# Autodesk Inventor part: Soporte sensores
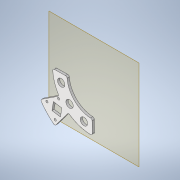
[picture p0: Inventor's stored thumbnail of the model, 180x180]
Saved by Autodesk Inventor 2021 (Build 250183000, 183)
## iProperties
Created: 2021-03
Part Number: Soporte sensores
Material: Genérico
Document SubType Name: Modeling
Designer: ATOUZA
Density: 1 g/cm^3
Appearance: Valor por defecto
Author: ATOUZA
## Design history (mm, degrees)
node "Plano de trabajo1"
sketch "Boceto1"
  geometry: L1 (-28.693, -55.468)-(-54.544, -30.413) reference; L2 (-79.599, -56.264)-(-53.748, -81.319) reference; L3 (0, 0)-(-54.146, -55.866); L4 (0, 0)-(-18.974, -75.514); L5 (0, 0)-(-74.556, -21.232); L6 (0, 0)-(-95.288, -1.49); L7 (0, 0)-(1.49, -95.288); L8 (-88.281, -84.164)-(-87.637, -83.606) reference; L9 (-87.223, -81.124)-(-87.653, -80.388) reference; L10 (-86.41, -79.502)-(-85.857, -80.148) reference; L11 (-83.375, -80.561)-(-82.642, -80.129) reference; L12 (-81.755, -81.37)-(-82.399, -81.927) reference; L13 (-82.813, -84.41)-(-82.383, -85.146) reference; L14 (-83.625, -86.032)-(-84.179, -85.386) reference; L15 (-86.661, -84.972)-(-87.393, -85.405) reference; L16 (-83.338, -78.485)-(-81.09, -78.859) reference; L17 (-84.256, -78.8)-(-83.441, -78.495) reference; L18 (-85.125, -78.214)-(-84.453, -78.767) reference; L19 (-87.467, -77.797)-(-85.219, -78.171) reference; L20 (-89.656, -74.985)-(-87.792, -77.595) reference; L21 (-89.622, -73.89)-(-89.743, -74.612) reference; L22 (-87.173, -73.791)-(-89.047, -73.479) reference; L23 (-86.548, -73.084)-(-86.597, -73.38) reference; L24 (-87.058, -72.796)-(-86.713, -72.854) reference; L25 (-87.008, -72.5)-(-87.058, -72.796) reference; L26 (-91.76, -71.506)-(-87.173, -72.27) reference; L27 (-94.25, -77.326)-(-93.486, -72.74) reference; L28 (-93.789, -77.606)-(-94.085, -77.557) reference; L29 (-93.847, -77.951)-(-93.789, -77.606) reference; L30 (-93.386, -78.231)-(-93.682, -78.181) reference; L31 (-92.499, -75.945)-(-92.811, -77.819) reference; L32 (-91.201, -75.655)-(-91.924, -75.534) reference; L33 (-89.012, -78.467)-(-90.877, -75.857) reference; L34 (-89.3, -81.087)-(-88.926, -78.839) reference; L35 (-88.985, -82.005)-(-89.29, -81.19) reference; L36 (-89.571, -82.874)-(-89.018, -82.202) reference; L37 (-89.988, -85.216)-(-89.613, -82.968) reference; L38 (-92.8, -87.405)-(-90.19, -85.541) reference; L39 (-93.895, -87.371)-(-93.173, -87.491) reference; L40 (-93.994, -84.922)-(-94.306, -86.796) reference; L41 (-94.701, -84.297)-(-94.405, -84.346) reference; L42 (-94.988, -84.807)-(-94.931, -84.461) reference; L43 (-95.284, -84.757)-(-94.988, -84.807) reference; L44 (-96.278, -89.509)-(-95.515, -84.922) reference; L45 (-90.458, -91.999)-(-95.045, -91.235) reference; L46 (-90.179, -91.538)-(-90.228, -91.834) reference; L47 (-89.834, -91.596)-(-90.179, -91.538) reference; L48 (-89.554, -91.135)-(-89.604, -91.431) reference; L49 (-91.84, -90.248)-(-89.965, -90.56) reference; L50 (-92.13, -88.95)-(-92.251, -89.673) reference; L51 (-89.318, -86.761)-(-91.928, -88.626) reference; L52 (-86.698, -87.049)-(-88.945, -86.675) reference; L53 (-85.78, -86.734)-(-86.595, -87.039) reference; L54 (-84.911, -87.32)-(-85.583, -86.767) reference; L55 (-82.569, -87.737)-(-84.817, -87.362) reference; L56 (-80.38, -90.549)-(-82.244, -87.939) reference; L57 (-80.414, -91.644)-(-80.293, -90.922) reference; L58 (-82.863, -91.743)-(-80.989, -92.055) reference; L59 (-83.488, -92.45)-(-83.438, -92.154) reference; L60 (-82.978, -92.737)-(-83.323, -92.68) reference; L61 (-83.027, -93.033)-(-82.978, -92.737) reference; L62 (-78.276, -94.027)-(-82.863, -93.263) reference; L63 (-75.786, -88.207)-(-76.55, -92.794) reference; L64 (-76.247, -87.928)-(-75.951, -87.977) reference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; C1 r 2 at (-54.146, -55.866) reference; C2 r 9 at (-54.146, -55.866); C3 r 9 at (-18.974, -75.514); C4 r 9 at (-74.556, -21.232); C5 r 9 at (-54.146, -55.866); C6 r 9 at (-18.974, -75.514); C7 r 2.75 at (-109.382, -78.709); C8 r 2.75 at (-80.96, -58.402); C9 r 2.75 at (-89.075, -107.131); C10 r 2.75 at (-89.075, -107.131); C11 r 2.75 at (-109.382, -78.709); C12 r 2.75 at (-80.96, -58.402); A1 r 60.3 centre (0, 0) between (-60.293, -0.943) and (0.943, -60.293); A2 r 95.3 centre (0, 0) between (-69.394, -65.319) and (-79.682, -52.277); A3 r 60.3 centre (0, 0) between (-60.293, -0.943) and (0.943, -60.293); A4 r 2.75 centre (-85.018, -82.767) between (-87.223, -81.124) and (-87.637, -83.606) reference; A5 r 3.55 centre (-85.018, -82.767) between (-86.41, -79.502) and (-87.653, -80.388) reference; A6 r 2.75 centre (-85.018, -82.767) between (-83.375, -80.561) and (-85.857, -80.148) reference; A7 r 3.55 centre (-85.018, -82.767) between (-81.755, -81.37) and (-82.642, -80.129) reference; A8 r 2.75 centre (-85.018, -82.767) between (-82.813, -84.41) and (-82.399, -81.927) reference; A9 r 3.55 centre (-85.018, -82.767) between (-83.625, -86.032) and (-82.383, -85.146) reference; A10 r 2.75 centre (-85.018, -82.767) between (-86.661, -84.972) and (-84.179, -85.386) reference; A11 r 3.55 centre (-85.018, -82.767) between (-88.281, -84.164) and (-87.393, -85.405) reference; A12 r 0.2 centre (-84.326, -78.613) between (-84.453, -78.767) and (-84.256, -78.8) reference; A13 r 0.2 centre (-85.252, -78.369) between (-85.125, -78.214) and (-85.219, -78.171) reference; A14 r 0.5 centre (-87.385, -77.304) between (-87.792, -77.595) and (-87.467, -77.797) reference; A15 r 0.5 centre (-89.249, -74.694) between (-89.743, -74.612) and (-89.656, -74.985) reference; A16 r 0.5 centre (-89.129, -73.972) between (-89.047, -73.479) and (-89.622, -73.89) reference; A17 r 0.5 centre (-87.091, -73.298) between (-87.173, -73.791) and (-86.597, -73.38) reference; A18 r 0.2 centre (-86.745, -73.051) between (-86.548, -73.084) and (-86.713, -72.854) reference; A19 r 0.2 centre (-87.206, -72.468) between (-87.008, -72.5) and (-87.173, -72.27) reference; A20 r 1.5 centre (-92.006, -72.986) between (-91.76, -71.506) and (-93.486, -72.74) reference; A21 r 0.2 centre (-94.052, -77.359) between (-94.25, -77.326) and (-94.085, -77.557) reference; A22 r 0.2 centre (-93.65, -77.984) between (-93.847, -77.951) and (-93.682, -78.181) reference; A23 r 0.5 centre (-93.304, -77.737) between (-93.386, -78.231) and (-92.811, -77.819) reference; A24 r 0.5 centre (-92.006, -76.027) between (-91.924, -75.534) and (-92.499, -75.945) reference; A25 r 0.5 centre (-91.283, -76.148) between (-90.877, -75.857) and (-91.201, -75.655) reference; A26 r 0.5 centre (-89.419, -78.757) between (-88.926, -78.839) and (-89.012, -78.467) reference; A27 r 0.2 centre (-89.103, -81.12) between (-89.3, -81.087) and (-89.29, -81.19) reference; A28 r 0.2 centre (-89.172, -82.075) between (-89.018, -82.202) and (-88.985, -82.005) reference; A29 r 0.5 centre (-90.481, -85.134) between (-90.19, -85.541) and (-89.988, -85.216) reference; A30 r 0.5 centre (-93.09, -86.998) between (-93.173, -87.491) and (-92.8, -87.405) reference; A31 r 0.5 centre (-93.813, -86.878) between (-94.306, -86.796) and (-93.895, -87.371) reference; A32 r 0.5 centre (-94.487, -84.84) between (-93.994, -84.922) and (-94.405, -84.346) reference; A33 r 0.2 centre (-94.734, -84.494) between (-94.701, -84.297) and (-94.931, -84.461) reference; A34 r 0.2 centre (-95.317, -84.955) between (-95.284, -84.757) and (-95.515, -84.922) reference; A35 r 1.5 centre (-94.799, -89.755) between (-96.278, -89.509) and (-95.045, -91.235) reference; A36 r 0.2 centre (-90.426, -91.801) between (-90.458, -91.999) and (-90.228, -91.834) reference; A37 r 0.2 centre (-89.801, -91.398) between (-89.834, -91.596) and (-89.604, -91.431) reference; A38 r 0.5 centre (-90.047, -91.053) between (-89.554, -91.135) and (-89.965, -90.56) reference; A39 r 0.5 centre (-91.757, -89.755) between (-92.251, -89.673) and (-91.84, -90.248) reference; A40 r 0.5 centre (-91.637, -89.032) between (-91.928, -88.626) and (-92.13, -88.95) reference; A41 r 0.5 centre (-89.028, -87.168) between (-88.945, -86.675) and (-89.318, -86.761) reference; A42 r 0.2 centre (-86.665, -86.852) between (-86.698, -87.049) and (-86.595, -87.039) reference; A43 r 0.2 centre (-85.71, -86.921) between (-85.583, -86.767) and (-85.78, -86.734) reference; A44 r 0.2 centre (-84.784, -87.165) between (-84.911, -87.32) and (-84.817, -87.362) reference; A45 r 0.5 centre (-82.651, -88.23) between (-82.244, -87.939) and (-82.569, -87.737) reference; A46 r 0.5 centre (-80.787, -90.839) between (-80.293, -90.922) and (-80.38, -90.549) reference; A47 r 0.5 centre (-80.907, -91.562) between (-80.989, -92.055) and (-80.414, -91.644) reference; A48 r 0.5 centre (-82.945, -92.236) between (-82.863, -91.743) and (-83.438, -92.154) reference; A49 r 0.2 centre (-83.29, -92.483) between (-83.488, -92.45) and (-83.323, -92.68) reference; A50 r 0.2 centre (-82.83, -93.066) between (-83.027, -93.033) and (-82.863, -93.263) reference; A51 r 1.5 centre (-78.03, -92.548) between (-78.276, -94.027) and (-76.55, -92.794) reference; A52 r 0.2 centre (-75.984, -88.174) between (-75.786, -88.207) and (-75.951, -87.977) reference; A53 r 0.2 centre (-76.386, -87.55) between (-76.189, -87.583) and (-76.354, -87.353) reference; A54 r 0.5 centre (-76.732, -87.796) between (-76.649, -87.303) and (-77.225, -87.714) reference; A55 r 0.5 centre (-78.03, -89.506) between (-78.112, -90) and (-77.537, -89.588) reference; A56 r 0.5 centre (-78.752, -89.386) between (-79.159, -89.677) and (-78.835, -89.879) reference; A57 r 0.5 centre (-80.617, -86.777) between (-81.11, -86.694) and (-81.024, -87.067) reference; A58 r 0.2 centre (-80.933, -84.414) between (-80.736, -84.447) and (-80.746, -84.344) reference; A59 r 0.2 centre (-80.864, -83.459) between (-81.018, -83.332) and (-81.051, -83.529) reference; A60 r 0.2 centre (-80.62, -82.533) between (-80.465, -82.66) and (-80.422, -82.565) reference; A61 r 0.5 centre (-79.555, -80.4) between (-79.846, -79.993) and (-80.048, -80.318) reference; A62 r 0.5 centre (-76.945, -78.535) between (-76.863, -78.042) and (-77.236, -78.129) reference; A63 r 0.5 centre (-76.223, -78.656) between (-75.73, -78.738) and (-76.141, -78.163) reference; A64 r 0.5 centre (-75.549, -80.694) between (-76.042, -80.612) and (-75.631, -81.187) reference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; 2 further points
  constraints: 40 end point, 18 centre point, 17 coincident, 17 point on circle, 6 midpoint, 5 point on line, 4 concentric, 3 parallel, 2 collinear, 2 perpendicular
  dimensions: "d0" = 18 diameter of C2; "d1" = 30 deg angle of L4 L3; "d2" = 18 diameter of C3; "d3" = 30 deg angle of L3 L5; "d4" = 18 diameter of C4; "d6" = 15 deg angle of L6 L5; "d7" = 15 deg angle of L7 L4; "d8" = 21 distance between parallel lines of L90 L88; "d9" = 21 distance between parallel lines of L91 L89; "d10" = 10 deg angle of L94 L95; "d12" = 150 radius of A74; "d14" = 10 deg angle of L96 L94; "d16" = 14.2 distance of L97.start L97.end; "d18" = 14.2 distance of L98.start L98.end; "d19" = 14.2 distance of L99.start L99.end; "d20" = 14.2 distance of L100.start L100.end; "d21" = 5.5 diameter of C7; "d22" = 5.5 diameter of C8; "d23" = 5.5 diameter of C9
extrude "Extrusión1" new body sketch "Boceto1" distance "d24" = 5.5; taper "d25" = 0 deg
fillet "Empalme1" dims "d26" = 4
node "Sólido1"
node "Referencia1"
node "Referencia2"
node "Referencia3"
node "Referencia4"
